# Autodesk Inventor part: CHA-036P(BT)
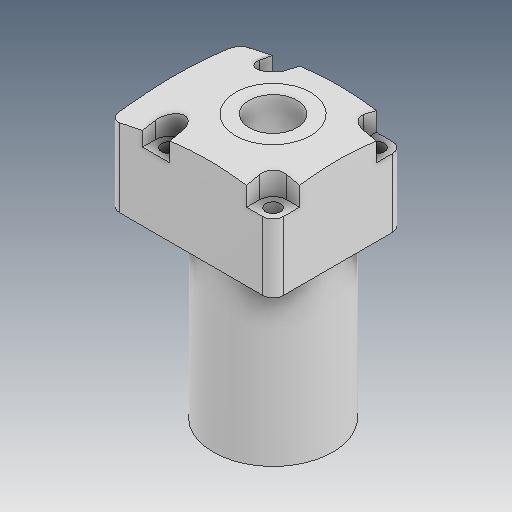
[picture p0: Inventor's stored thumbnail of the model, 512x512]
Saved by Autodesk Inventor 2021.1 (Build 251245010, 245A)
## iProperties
Created: 2021-05
Part Number: CHA-036P(BT)
Material: Ogólny
Document SubType Name: Modeling
Designer: user
Density: 1 g/cm^3
Appearance: Domyślna
Author: user
Revision Number: ÈÎºÎ
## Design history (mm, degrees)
feature "ÇÐ³ý-À­Éì6"
node "Bryła1"
